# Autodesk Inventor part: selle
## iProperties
Shininess: 69.0
Length Units: 11269
Angle Units: 11279
Time Units: 11290
Mass Units: 11283
Length Display Precision: 3
Angle Display Precision: 2
Compacted: True
Created: 2001-12
Part Number: selle
Material: Par défaut
Document SubType Name: Tôlerie
Designer: pichon
Density: 0.0
Volumn: 0.0
Area: 0.0
PropertySet Name: Model Information
Control State: 0
Master: False
Checked Out: False
Author: pichon
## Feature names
1. Pli2
2. Extrusion1
3. Extrusion2
4. Révolution1 [Revolution]
5. Extrusion3
6. Plaque1
7. Plaque2
8. Pli1
9. Plaque3
10. Pli3
